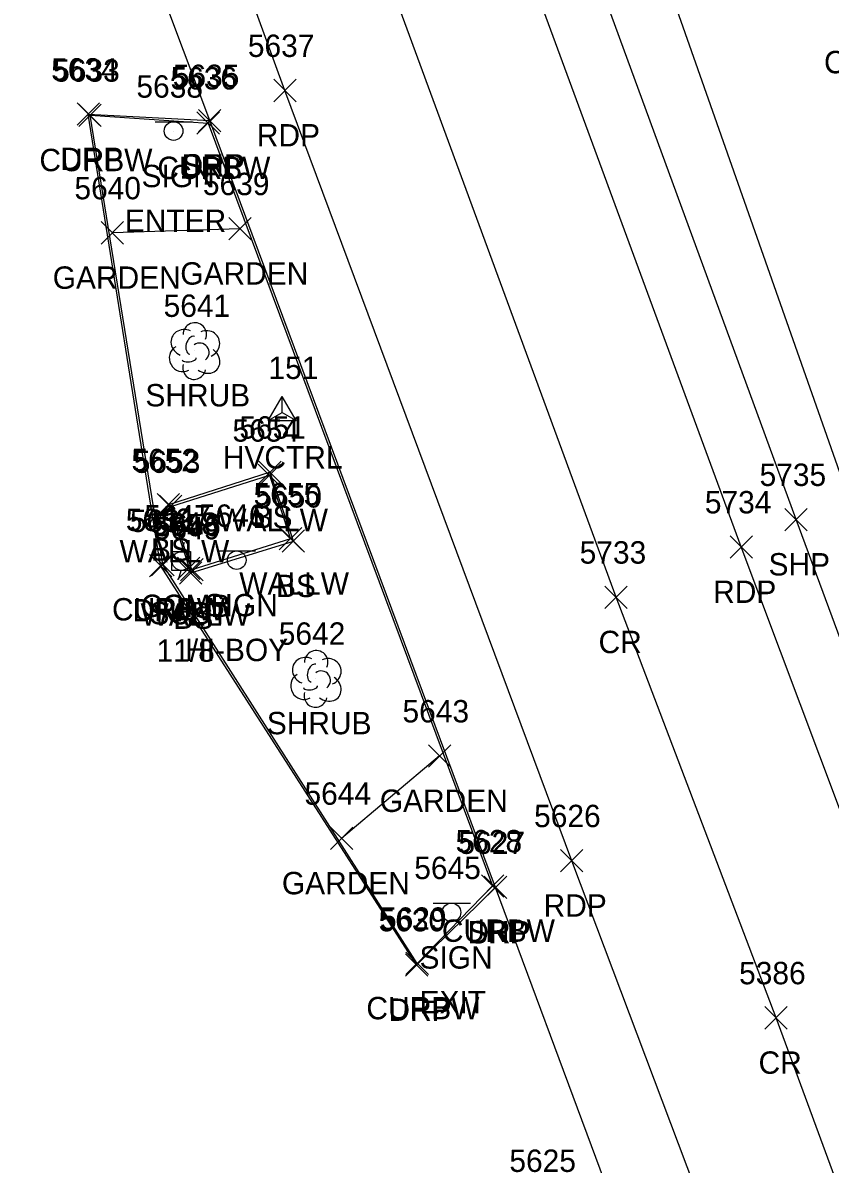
# Model space of a CAD drawing. Extents: x 1769141 to 1770911, y 735471 to 741449.
# Drawn here: x 1770459.6 to 1770531.7, y 739925.6 to 740027.6 of the extents above; entities that cross this region are included whole.
import ezdxf

# ---------------------------------------------------------------- set-up
doc = ezdxf.new("R2010")
doc.units = 0
for name, color, linetype in [('C_A', 7, 'Continuous'), ('C_I', 7, 'Continuous'), ('CPSM', 7, 'Continuous'), ('DCP', 7, 'Continuous'), ('L_A', 7, 'Continuous'), ('L_I', 7, 'Continuous'), ('L_TIC', 7, 'Continuous'), ('LAPB', 7, 'Continuous'), ('LELB', 7, 'Continuous'), ('LSH', 7, 'Continuous'), ('LW', 7, 'Continuous'), ('P_A', 7, 'Continuous'), ('P_I', 7, 'Continuous'), ('P_TIC', 7, 'Continuous'), ('PET', 7, 'Continuous'), ('PRC', 7, 'Continuous'), ('PSP', 7, 'Continuous'), ('R_A', 7, 'Continuous'), ('R_I', 7, 'Continuous'), ('R_TIC', 7, 'Continuous'), ('RC', 7, 'Continuous'), ('RDP', 7, 'Continuous'), ('S_A', 7, 'Continuous'), ('S_C', 7, 'Continuous'), ('S_I', 7, 'Continuous'), ('SSGN', 7, 'Continuous'), ('U_A', 7, 'Continuous'), ('U_C', 7, 'Continuous'), ('U_I', 7, 'Continuous'), ('U_TIC', 7, 'Continuous'), ('UP', 7, 'Continuous')]:
    doc.layers.add(name, color=color, linetype=linetype)

msp = doc.modelspace()

# ---------------------------------------------------------------- linework, layer by layer
at = {"layer": 'CPSM'}
for p, q in [((1770481.49, 739992.06), (1770482.74, 739994.23)), ((1770483.99, 739992.06), (1770482.74, 739994.23)), ((1770482.74, 739992.78), (1770482.74, 739994.23)), ((1770481.49, 739992.06), (1770482.74, 739992.78)), ((1770482.74, 739992.78), (1770482.74, 739992.78)), ((1770482.74, 739992.78), (1770483.99, 739992.06)), ((1770481.49, 739992.06), (1770483.99, 739992.06))]:
    msp.add_line(p, q, dxfattribs=at)
at = {"layer": 'DCP'}
msp.add_lwpolyline([(1770586.82, 739833.24), (1770441.42, 740246.45)], dxfattribs=at)
at = {"layer": 'L_TIC'}
for points in [[(1770466.56, 740007.84), (1770468.56, 740009.84)], [(1770468.56, 740007.84), (1770466.56, 740009.84)], [(1770477.96, 740008.21), (1770479.96, 740010.21)], [(1770479.96, 740008.21), (1770477.96, 740010.21)], [(1770480.65, 739986.45), (1770482.65, 739988.45)], [(1770482.65, 739986.45), (1770480.65, 739988.45)], [(1770480.6, 739986.18), (1770482.6, 739988.18)], [(1770482.6, 739986.18), (1770480.6, 739988.18)], [(1770471.57, 739983.54), (1770473.57, 739985.54)], [(1770473.57, 739983.54), (1770471.57, 739985.54)], [(1770471.78, 739983.39), (1770473.78, 739985.39)], [(1770473.78, 739983.39), (1770471.78, 739985.39)], [(1770482.48, 739980.5), (1770484.48, 739982.5)], [(1770484.48, 739980.5), (1770482.48, 739982.5)], [(1770482.74, 739980.29), (1770484.74, 739982.29)], [(1770484.74, 739980.29), (1770482.74, 739982.29)], [(1770473.57, 739977.45), (1770475.57, 739979.45)], [(1770475.57, 739977.45), (1770473.57, 739979.45)], [(1770473.66, 739977.73), (1770475.66, 739979.73)], [(1770475.66, 739977.73), (1770473.66, 739979.73)], [(1770495.8, 739961.09), (1770497.8, 739963.09)], [(1770497.8, 739961.09), (1770495.8, 739963.09)], [(1770487.04, 739953.73), (1770489.04, 739955.73)], [(1770489.04, 739953.73), (1770487.04, 739955.73)]]:
    msp.add_lwpolyline(points, dxfattribs=at)
at = {"layer": 'LAPB'}
for points in [[(1770478.96, 740009.21), (1770467.56, 740008.84)], [(1770496.8, 739962.09), (1770488.04, 739954.73)]]:
    msp.add_lwpolyline(points, dxfattribs=at)
at = {"layer": 'LELB'}
for points in [[(1770474.57, 739978.45), (1770483.74, 739981.29), (1770481.65, 739987.45), (1770472.57, 739984.54)], [(1770472.57, 739984.54), (1770474.57, 739978.45)]]:
    msp.add_lwpolyline(points, dxfattribs=at)
at = {"layer": 'LSH'}
for p, q in [((1770474.88, 739998.33), (1770474.88, 739998.33)), ((1770474.88, 739998.33), (1770474.88, 739998.33)), ((1770485.73, 739969.03), (1770485.73, 739969.03)), ((1770485.73, 739969.03), (1770485.73, 739969.03))]:
    msp.add_line(p, q, dxfattribs=at)
for centre in [(1770474.93, 739999.76), (1770485.78, 739970.46)]:
    msp.add_arc(centre, 1.05, 335.5272, 180.9563, dxfattribs=at)
for centre, major_axis, ratio, start_param, end_param in [((1770474.09, 739999), (1.21, -0.51), 0.895232, 1.570796, 4.712389), ((1770474.68, 739998.79), (-0.208, -0.792), 0.645439, 3.141593, 6.283185), ((1770475.93, 739998.91), (-1.14, -0.48), 0.949671, 1.570796, 4.712389), ((1770473.8, 739997.62), (0.58, -1.04), 0.959034, 3.141593, 6.283185), ((1770475.38, 739998.16), (-0.5, 0.667), 0.989748, 3.141593, 6.283185), ((1770474.43, 739997.58), (-0.625, -0.083), 0.423636, 0, 3.141593), ((1770475.89, 739997.5), (-1.09, 0.79), 0.841452, 1.570796, 4.712389), ((1770474.89, 739996.83), (0.26, 1.06), 0.942809, 1.570796, 4.712389), ((1770484.94, 739969.7), (1.21, -0.51), 0.895232, 1.570796, 4.712389), ((1770486.78, 739969.61), (-1.14, -0.48), 0.949671, 1.570796, 4.712389), ((1770485.53, 739969.49), (-0.208, -0.792), 0.645439, 3.141593, 6.283185), ((1770484.65, 739968.32), (0.58, -1.04), 0.959034, 3.141593, 6.283185), ((1770486.23, 739968.86), (-0.5, 0.667), 0.989748, 3.141593, 6.283185), ((1770486.73, 739968.2), (-1.09, 0.79), 0.841452, 1.570796, 4.712389), ((1770485.28, 739968.28), (-0.625, -0.083), 0.423636, 0, 3.141593), ((1770485.73, 739967.53), (0.26, 1.06), 0.942809, 1.570796, 4.712389)]:
    msp.add_ellipse(centre, major_axis=major_axis, ratio=ratio, start_param=start_param, end_param=end_param, dxfattribs=at)
at = {"layer": 'LW'}
for points in [[(1770472.78, 739984.39), (1770481.6, 739987.18), (1770483.48, 739981.5), (1770474.66, 739978.73)], [(1770474.66, 739978.73), (1770472.78, 739984.39)]]:
    msp.add_lwpolyline(points, dxfattribs=at)
at = {"layer": 'P_TIC'}
for points in [[(1770481.98, 740020.56), (1770483.98, 740022.56)], [(1770483.98, 740020.56), (1770481.98, 740022.56)], [(1770475.26, 740017.87), (1770477.26, 740019.87)], [(1770477.26, 740017.87), (1770475.26, 740019.87)], [(1770527.66, 739982.22), (1770529.66, 739984.22)], [(1770529.66, 739982.22), (1770527.66, 739984.22)], [(1770522.77, 739979.77), (1770524.77, 739981.77)], [(1770524.77, 739979.77), (1770522.77, 739981.77)], [(1770511.58, 739975.28), (1770513.58, 739977.28)], [(1770513.58, 739975.28), (1770511.58, 739977.28)], [(1770507.61, 739951.73), (1770509.61, 739953.73)], [(1770509.61, 739951.73), (1770507.61, 739953.73)], [(1770500.8, 739949.34), (1770502.8, 739951.34)], [(1770502.8, 739949.34), (1770500.8, 739951.34)], [(1770525.88, 739937.69), (1770527.88, 739939.69)], [(1770527.88, 739937.69), (1770525.88, 739939.69)]]:
    msp.add_lwpolyline(points, dxfattribs=at)
at = {"layer": 'PET'}
for points in [[(1770553.27, 739901.7), (1770537.83, 739943.38), (1770523.77, 739980.77), (1770499.87, 740045.65), (1770491.21, 740069), (1770475.98, 740110.18), (1770458, 740159.65), (1770443.67, 740199.3), (1770424.08, 740251.17), (1770412.7, 740282.67), (1770395.6, 740328.61), (1770379.16, 740373.29), (1770360.22, 740424.51)], [(1770526.99, 739903.96), (1770508.61, 739952.73), (1770482.98, 740021.56), (1770465.73, 740068.87), (1770446.91, 740120.21), (1770436.39, 740149.2), (1770420.1, 740193.45), (1770401.33, 740243.92), (1770375.13, 740314.06), (1770354.08, 740371.38), (1770337.26, 740416.85)]]:
    msp.add_lwpolyline(points, dxfattribs=at)
at = {"layer": 'PRC'}
msp.add_lwpolyline([(1770544.53, 739890.8), (1770526.88, 739938.69), (1770512.58, 739976.28), (1770488.64, 740041.4), (1770480.72, 740062.92), (1770464.76, 740106.43), (1770446.69, 740155.46), (1770432.25, 740194.74), (1770412.72, 740247.51), (1770400.4, 740280.65), (1770384.57, 740323.92), (1770366.94, 740369.74), (1770348.35, 740420.63)], dxfattribs=at)
at = {"layer": 'PSP'}
for points in [[(1770540.34, 739951.65), (1770528.66, 739983.22), (1770504.99, 740047.85), (1770496.22, 740070.8), (1770481.82, 740111.56), (1770464.17, 740161.25), (1770449.88, 740201.4), (1770429.3, 740252.9), (1770418.04, 740283.83), (1770400.74, 740330.55), (1770384.34, 740374.74), (1770365.93, 740426.73), (1770363, 740434.14), (1770343.37, 740484.07), (1770326.57, 740533.85), (1770310.21, 740576.26), (1770285.85, 740639.32), (1770267.25, 740691.65), (1770245.28, 740742.42), (1770222.4, 740793.58), (1770203.84, 740840.26), (1770179.15, 740903.22)], [(1770519.72, 739902.09), (1770501.8, 739950.34), (1770476.26, 740018.87), (1770458.57, 740065.96), (1770452.77, 740080.17), (1770447.86, 740094.08), (1770439.07, 740117.75), (1770428.15, 740148.24), (1770412.39, 740191.86), (1770394.34, 740240.88), (1770368.09, 740312), (1770346.98, 740368.28), (1770329.75, 740414.99)]]:
    msp.add_lwpolyline(points, dxfattribs=at)
at = {"layer": 'R_TIC'}
for points in [[(1770464.4, 740018.45), (1770466.4, 740020.45)], [(1770466.4, 740018.45), (1770464.4, 740020.45)], [(1770464.57, 740018.35), (1770466.57, 740020.35)], [(1770466.57, 740018.35), (1770464.57, 740020.35)], [(1770475.12, 740017.65), (1770477.12, 740019.65)], [(1770477.12, 740017.65), (1770475.12, 740019.65)], [(1770475.26, 740017.87), (1770477.26, 740019.87)], [(1770477.26, 740017.87), (1770475.26, 740019.87)], [(1770470.87, 739978.11), (1770472.87, 739980.11)], [(1770472.87, 739978.11), (1770470.87, 739980.11)], [(1770471.07, 739978.2), (1770473.07, 739980.2)], [(1770473.07, 739978.2), (1770471.07, 739980.2)], [(1770500.54, 739949.48), (1770502.54, 739951.48)], [(1770502.54, 739949.48), (1770500.54, 739951.48)], [(1770500.8, 739949.34), (1770502.8, 739951.34)], [(1770502.8, 739949.34), (1770500.8, 739951.34)], [(1770493.75, 739942.42), (1770495.75, 739944.42)], [(1770495.75, 739942.42), (1770493.75, 739944.42)], [(1770493.8, 739942.56), (1770495.8, 739944.56)], [(1770495.8, 739942.56), (1770493.8, 739944.56)]]:
    msp.add_lwpolyline(points, dxfattribs=at)
at = {"layer": 'RC'}
for points in [[(1770501.54, 739950.48), (1770494.8, 739943.56), (1770472.07, 739979.2), (1770465.57, 740019.35), (1770476.12, 740018.65)], [(1770476.12, 740018.65), (1770501.54, 739950.48)]]:
    msp.add_lwpolyline(points, dxfattribs=at)
at = {"layer": 'RDP'}
msp.add_lwpolyline([(1770501.8, 739950.34), (1770494.75, 739943.42), (1770471.87, 739979.11), (1770465.4, 740019.45), (1770476.26, 740018.87)], dxfattribs=at)
at = {"layer": 'SSGN'}
for p, q in [((1770471.39, 740018.77), (1770474.72, 740018.77)), ((1770473.03, 740017.94), (1770473.03, 740017.94)), ((1770477.03, 739980.42), (1770480.36, 739980.42)), ((1770478.67, 739979.59), (1770478.67, 739979.59)), ((1770496.22, 739948.95), (1770499.56, 739948.95)), ((1770497.87, 739948.11), (1770497.87, 739948.11))]:
    msp.add_line(p, q, dxfattribs=at)
for centre in [(1770473.03, 740017.94), (1770478.67, 739979.59), (1770497.87, 739948.11)]:
    msp.add_circle(centre, 0.833, dxfattribs=at)
at = {"layer": 'U_TIC'}
for points in [[(1770473.38, 739977.85), (1770475.38, 739979.85)], [(1770475.38, 739977.85), (1770473.38, 739979.85)]]:
    msp.add_lwpolyline(points, dxfattribs=at)
at = {"layer": 'UP'}
for p, q in [((1770473.97, 739981.18), (1770473.72, 739980.35)), ((1770472.88, 739978.68), (1770472.88, 739980.35)), ((1770472.88, 739980.35), (1770474.55, 739980.35)), ((1770474.55, 739980.35), (1770474.55, 739978.68)), ((1770473.72, 739979.51), (1770473.72, 739979.51)), ((1770474.55, 739978.68), (1770472.88, 739978.68)), ((1770473.47, 739977.85), (1770473.72, 739978.68))]:
    msp.add_line(p, q, dxfattribs=at)
msp.add_circle((1770473.72, 739979.51), 0.833, dxfattribs=at)

# ---------------------------------------------------------------- texts
at = {"layer": 'C_A'}
msp.add_text('HVCTRL', height=2, dxfattribs=at).set_placement((1770477.43, 739987.78))
at = {"layer": 'C_I'}
msp.add_text('151', height=2, dxfattribs=at).set_placement((1770481.51, 739995.78))
at = {"layer": 'L_A'}
for s, p in [('GARDEN', (1770462.23, 740003.84)), ('GARDEN', (1770473.63, 740004.21)), ('SHRUB', (1770470.51, 739993.33)), ('BS', (1770480.09, 739982.45)), ('WALLW', (1770477.02, 739982.18)), ('WALLW', (1770468.2, 739979.39)), ('BS', (1770471.01, 739979.54)), ('WALLW', (1770478.9, 739976.5)), ('BS', (1770482.18, 739976.29)), ('WALLW', (1770470.08, 739973.73)), ('BS', (1770473.01, 739973.45)), ('SHRUB', (1770481.36, 739964.03)), ('GARDEN', (1770491.46, 739957.09)), ('GARDEN', (1770482.71, 739949.73))]:
    msp.add_text(s, height=2, dxfattribs=at).set_placement(p)
at = {"layer": 'L_I'}
for s, p in [('5640', (1770464.17, 740011.84)), ('5639', (1770475.65, 740012.21)), ('5641', (1770472.14, 740001.33)), ('5651', (1770478.91, 739990.45)), ('5654', (1770478.29, 739990.18)), ('5652', (1770469.26, 739987.54)), ('5653', (1770469.47, 739987.39)), ('5655', (1770480.18, 739984.5)), ('5650', (1770480.34, 739984.29)), ('5649', (1770471.26, 739981.45)), ('5656', (1770471.3, 739981.73)), ('5642', (1770482.43, 739972.03)), ('5643', (1770493.49, 739965.09)), ('5644', (1770484.73, 739957.73)), ('5625', (1770503.04, 739924.92))]:
    msp.add_text(s, height=2, dxfattribs=at).set_placement(p)
at = {"layer": 'P_A'}
for s, p in [('RDP', (1770480.47, 740016.56)), ('SHP', (1770473.8, 740013.87)), ('SHP', (1770526.2, 739978.22)), ('RDP', (1770521.25, 739975.77)), ('CR', (1770511.01, 739971.28)), ('RDP', (1770506.1, 739947.73)), ('SHP', (1770499.34, 739945.34)), ('CR', (1770525.31, 739933.69))]:
    msp.add_text(s, height=2, dxfattribs=at).set_placement(p)
at = {"layer": 'P_I'}
for s, p in [('5637', (1770479.67, 740024.56)), ('5635', (1770472.96, 740021.87)), ('5735', (1770525.4, 739986.22)), ('5734', (1770520.51, 739983.77)), ('5733', (1770509.32, 739979.28)), ('5626', (1770505.25, 739955.73)), ('5627', (1770498.49, 739953.34)), ('5386', (1770523.57, 739941.69))]:
    msp.add_text(s, height=2, dxfattribs=at).set_placement(p)
at = {"layer": 'R_A'}
for s, p in [('CURBW', (1770531.16, 740023.1)), ('CURBW', (1770461.04, 740014.35)), ('DRP', (1770462.89, 740014.45)), ('DRP', (1770473.75, 740013.87)), ('CURBW', (1770471.58, 740013.65)), ('CURBW', (1770467.53, 739974.2)), ('DRP', (1770469.36, 739974.11)), ('CURBW', (1770497.01, 739945.48)), ('DRP', (1770499.29, 739945.34)), ('CURBW', (1770490.26, 739938.56)), ('DRP', (1770492.23, 739938.42))]:
    msp.add_text(s, height=2, dxfattribs=at).set_placement(p)
at = {"layer": 'R_I'}
for s, p in [('5634', (1770462.09, 740022.45)), ('5633', (1770462.27, 740022.35)), ('5636', (1770472.76, 740021.65)), ('5635', (1770472.96, 740021.87)), ('5632', (1770468.76, 739982.2)), ('5631', (1770469.13, 739982.11)), ('5628', (1770498.23, 739953.48)), ('5627', (1770498.49, 739953.34)), ('5629', (1770491.48, 739946.56)), ('5630', (1770491.35, 739946.42))]:
    msp.add_text(s, height=2, dxfattribs=at).set_placement(p)
at = {"layer": 'S_A'}
for p in [(1770470.17, 740012.92), (1770475.81, 739974.57), (1770495.01, 739943.09)]:
    msp.add_text('SIGN', height=2, dxfattribs=at).set_placement(p)
at = {"layer": 'S_C'}
for s, p in [('ENTER', (1770468.67, 740008.92)), ('HI-BOY', (1770474.06, 739970.57)), ('EXIT', (1770495.01, 739939.09))]:
    msp.add_text(s, height=2, dxfattribs=at).set_placement(p)
at = {"layer": 'S_I'}
for s, p in [('5638', (1770469.71, 740020.92)), ('5646', (1770475.29, 739982.57)), ('5645', (1770494.54, 739951.09))]:
    msp.add_text(s, height=2, dxfattribs=at).set_placement(p)
at = {"layer": 'U_A'}
for s, p in [('COMB', (1770470.1, 739974.51)), ('SUBT', (1770470.87, 739973.85))]:
    msp.add_text(s, height=2, dxfattribs=at).set_placement(p)
at = {"layer": 'U_C'}
msp.add_text('11/8', height=2, dxfattribs=at).set_placement((1770471.51, 739970.51))
at = {"layer": 'U_I'}
for s, p in [('5647', (1770470.41, 739982.51)), ('5648', (1770471.07, 739981.85))]:
    msp.add_text(s, height=2, dxfattribs=at).set_placement(p)

doc.saveas('drawing.dxf')
